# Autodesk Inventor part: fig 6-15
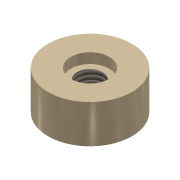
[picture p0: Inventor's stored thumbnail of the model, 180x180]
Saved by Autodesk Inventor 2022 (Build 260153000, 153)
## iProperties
Created: 2001-11
Part Number: fig 6-15
Document SubType Name: Modeling
Designer: Renu Muthoo
Density: 1 g/cm^3
Material: Generic
Appearance: Metal-Titanium (Polished)
Control State: 0
Master: False
Checked Out: False
Shininess: 65.0
Angle Display Precision: 2
Document Length Units: 11269
Document Angle Units: 11279
Document Time Units: 11290
Document Mass Units: 11283
Document Length Units Precision: 3
Document Angle Units Precision: 2
Density: 0.0
Volumn: 0.0
Area: 0.0
PropertySet Name: Model Information
Author: Renu Muthoo
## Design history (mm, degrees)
sketch "Sketch1"
  geometry: C1 r 16.401 at (0, 0)
  constraints: 1 centre point
extrude "Extrusion1" new body sketch "Sketch1" distance "d0" = 15; taper "d1" = 0 deg
hole "Hole3" diameter "d18" = 10.106; stored, may be unused: countersink angle "d22" = 90 deg, drill point angle "d24" = 118 deg; dims "d16" = 10, "d17" = 10, "d19" = 6, "d20" = 15, "d21" = 4, "d23" = 10
body "Solid1"
